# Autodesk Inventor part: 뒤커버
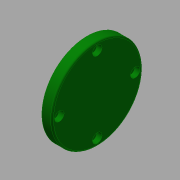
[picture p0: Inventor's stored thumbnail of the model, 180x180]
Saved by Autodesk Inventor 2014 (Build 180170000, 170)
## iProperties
Created: 2015-09
Part Number: 뒤커버
Material: 알루미늄 6061
Document SubType Name: Modeling
Designer: mduedu
Density: 2.71 g/cm^3
Mass: 54.0417 g
Surface Area: 84.9688 cm^2
Volume: 19.9416 cm^3
Appearance: 진녹색
Author: mduedu
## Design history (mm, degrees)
sketch "스케치1"
  geometry: L1 (-15.5, 47)-(-15.5, 78); L2 (-15.5, 78)-(-22.5, 78); L3 (-22.5, 78)-(-22.5, 67); L4 (-25.5, 67)-(-25.5, 47); L5 (-79.5, 39.5)-(-79.5, 54.5) reference; L6 (48.5, 54.5)-(48.5, 39.5) reference; L7 (-79.5, 47)-(48.5, 47); L8 (-22.5, 67)-(-25.5, 67); L9 (-25.5, 47)-(-15.5, 47); 1 further point
  constraints: 14 end point, 4 midpoint, 3 parallel, 1 collinear, 1 point on line, 1 vertical
  dimensions: "d6" = 62 diameter of L2 L7; "d7" = 7 distance of L1.end L2.end; "d8" = 40 diameter of L3.end L7; "d32" = 10 distance between parallel lines of L1 L4
revolve "회전1" sketch "스케치1" stored, may be unused: angle "d4" = 90 deg
sketch "스케치4"
  geometry: C1 r 31 at (0, 0) reference; 2 further points
  constraints: 1 coincident
hole "구멍3" sketch "스케치4" at (0, 0) diameter "d33" = 33; stored, may be unused: countersink angle "d37" = 90 deg, drill point angle "d39" = 0 deg; dims "d34" = 6, "d35" = 4, "d36" = 2, "d38" = 5
fillet "모깎기4" dims "d40" = 1
chamfer "모따기2" distance "d41" = 1; stored, may be unused: second distance "d42" = 2, angle "d43" = 45 deg
sketch "스케치6" dims "d56" = 52
  geometry: C1 r 31 at (0, 0) reference; 5 further points
  constraints: 2 vertical alignment, 1 coincident, 7 other
  dimensions: "d59" = 360 deg dimension on C1.centre point (0, 26) (derived)
hole "구멍4" sketch "스케치6" at (0, 26), (-26, 0), (0, -26), (26, 0) diameter "d49" = 3.4; stored, may be unused: countersink angle "d53" = 90 deg, drill point angle "d55" = 0 deg; dims "d50" = 6, "d51" = 6.5, "d52" = 3.4, "d54" = 8
node "솔리드1"
node "참조1"
node "참조2"
